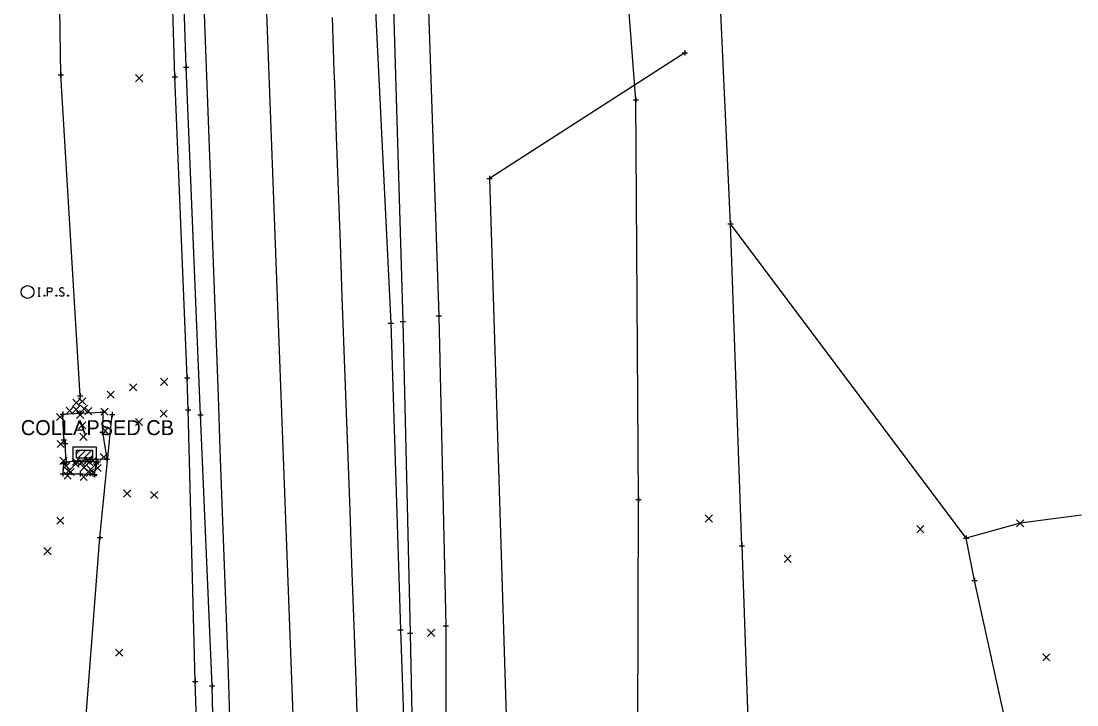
# Model space of a CAD drawing. Extents: x 146022 to 147632, y 437624 to 440659.
# Drawn here: x 146969.6 to 147167.5, y 438729.9 to 438858 of the extents above; entities that cross this region are included whole.
import ezdxf

# ---------------------------------------------------------------- set-up
doc = ezdxf.new("R2010")
doc.units = 0
for name, color, linetype in [('_CIVIL_CONSTRUCTION', 7, 'Continuous'), ('BR_P_Rail_Object', 7, 'Continuous'), ('DR_P_Ditch', 7, 'Continuous'), ('DR_P_Paved_Gutter', 7, 'Continuous'), ('DT_X_Triangles', 7, 'Continuous'), ('PF_X_Ground_Line', 7, 'Continuous'), ('PV_P_Curb', 7, 'Continuous'), ('PV_P_Saw_Cut_Line', 7, 'Continuous'), ('PV_P_Shoulder', 7, 'Continuous'), ('RD_P_Anchor_Assembly', 7, 'Continuous'), ('RD_P_Fence', 7, 'Continuous'), ('RD_P_GR_Lt_Replaced', 7, 'Continuous'), ('SC_Scratch3', 7, 'Continuous'), ('SV_X_Terrain_Boundary', 7, 'Continuous'), ('UT_X_Electric', 7, 'Continuous')]:
    doc.layers.add(name, color=color, linetype=linetype)

msp = doc.modelspace()

# ---------------------------------------------------------------- linework, layer by layer
at = {"layer": '_CIVIL_CONSTRUCTION'}
for p, q in [((146991.1, 438846.68), (146992.43, 438848.02)), ((146991.1, 438848.02), (146992.43, 438846.68)), ((146995.79, 438789.8), (146997.12, 438791.13)), ((146995.79, 438791.13), (146997.12, 438789.8)), ((146985.76, 438787.39), (146987.1, 438788.72)), ((146985.76, 438788.72), (146987.1, 438787.39)), ((146989.96, 438788.77), (146991.3, 438790.1)), ((146989.96, 438790.1), (146991.3, 438788.77)), ((146979.32, 438785.87), (146980.65, 438787.21)), ((146979.32, 438787.21), (146980.65, 438785.87)), ((146980.42, 438786.12), (146981.75, 438787.45)), ((146980.42, 438787.45), (146981.75, 438786.12)), ((146976.3, 438783.22), (146977.63, 438784.55)), ((146976.3, 438784.55), (146977.63, 438783.22)), ((146978.08, 438784.4), (146979.42, 438785.73)), ((146978.08, 438785.73), (146979.42, 438784.4)), ((146979.3, 438784.6), (146980.63, 438785.93)), ((146979.3, 438785.93), (146980.63, 438784.6)), ((146980.04, 438783.56), (146981.37, 438784.9)), ((146980.04, 438784.9), (146981.37, 438783.56)), ((146980.78, 438784.73), (146982.11, 438786.07)), ((146980.78, 438786.07), (146982.11, 438784.73)), ((146981.57, 438784.28), (146982.91, 438785.62)), ((146981.57, 438785.62), (146982.91, 438784.28)), ((146984.6, 438784.21), (146985.93, 438785.55)), ((146984.6, 438785.55), (146985.93, 438784.21)), ((146995.7, 438783.82), (146997.03, 438785.16)), ((146995.7, 438785.16), (146997.03, 438783.82)), ((146980.43, 438781.66), (146981.76, 438782.99)), ((146980.43, 438782.99), (146981.76, 438781.66)), ((146991.05, 438782.26), (146992.38, 438783.6)), ((146991.05, 438783.6), (146992.38, 438782.26)), ((146980.67, 438779.48), (146982, 438780.81)), ((146980.67, 438780.81), (146982, 438779.48)), ((146984.78, 438780.61), (146986.11, 438781.95)), ((146984.78, 438781.95), (146986.11, 438780.61)), ((146976.39, 438778.13), (146977.72, 438779.46)), ((146976.39, 438779.46), (146977.72, 438778.13)), ((146984.49, 438775.71), (146985.82, 438777.04)), ((146984.49, 438777.04), (146985.82, 438775.71)), ((146976.92, 438774.99), (146978.25, 438776.33)), ((146976.92, 438776.33), (146978.25, 438774.99)), ((146977.43, 438774.01), (146978.76, 438775.34)), ((146977.43, 438775.34), (146978.76, 438774.01)), ((146979.19, 438774.38), (146980.52, 438775.72)), ((146979.19, 438775.72), (146980.52, 438774.38)), ((146979.29, 438774.82), (146980.63, 438776.16)), ((146979.29, 438776.16), (146980.63, 438774.82)), ((146980.24, 438774.64), (146981.58, 438775.97)), ((146980.24, 438775.97), (146981.58, 438774.64)), ((146980.76, 438773.7), (146982.09, 438775.04)), ((146980.76, 438775.04), (146982.09, 438773.7)), ((146981.47, 438775.01), (146982.81, 438776.35)), ((146981.47, 438776.35), (146982.81, 438775.01)), ((146981.77, 438774.8), (146983.1, 438776.14)), ((146981.77, 438776.14), (146983.1, 438774.8)), ((146982, 438773.37), (146983.34, 438774.71)), ((146982, 438774.71), (146983.34, 438773.37)), ((146982.44, 438775.02), (146983.78, 438776.35)), ((146982.44, 438776.35), (146983.78, 438775.02)), ((146983.33, 438773.64), (146984.66, 438774.98)), ((146983.33, 438774.98), (146984.66, 438773.64)), ((146977.71, 438772.19), (146979.04, 438773.53)), ((146977.71, 438773.53), (146979.04, 438772.19)), ((146977.85, 438773.06), (146979.19, 438774.39)), ((146977.85, 438774.39), (146979.19, 438773.06)), ((146978.23, 438772.88), (146979.57, 438774.22)), ((146978.23, 438774.22), (146979.57, 438772.88)), ((146980.72, 438772), (146982.05, 438773.34)), ((146980.72, 438773.34), (146982.05, 438772)), ((146981.85, 438772.74), (146983.19, 438774.07)), ((146981.85, 438774.07), (146983.19, 438772.74)), ((146982.47, 438772.79), (146983.8, 438774.13)), ((146982.47, 438774.13), (146983.8, 438772.79)), ((146988.86, 438768.87), (146990.19, 438770.2)), ((146988.86, 438770.2), (146990.19, 438768.87)), ((146993.92, 438768.59), (146995.25, 438769.92)), ((146993.92, 438769.92), (146995.25, 438768.59)), ((146976.33, 438763.79), (146977.66, 438765.12)), ((146976.33, 438765.12), (146977.66, 438763.79)), ((147097.85, 438764.19), (147099.18, 438765.53)), ((147097.85, 438765.53), (147099.18, 438764.19)), ((147156.18, 438763.29), (147157.51, 438764.62)), ((147156.18, 438764.62), (147157.51, 438763.29)), ((147137.49, 438762.18), (147138.82, 438763.51)), ((147137.49, 438763.51), (147138.82, 438762.18)), ((146973.93, 438758.06), (146975.26, 438759.39)), ((146973.93, 438759.39), (146975.26, 438758.06)), ((147112.59, 438756.63), (147113.93, 438757.97)), ((147112.59, 438757.97), (147113.93, 438756.63)), ((147045.82, 438742.77), (147047.16, 438744.11)), ((147045.82, 438744.11), (147047.16, 438742.77)), ((146987.36, 438739.03), (146988.7, 438740.36)), ((146987.36, 438740.36), (146988.7, 438739.03)), ((147161.08, 438738.19), (147162.41, 438739.52)), ((147161.08, 438739.52), (147162.41, 438738.19))]:
    msp.add_line(p, q, dxfattribs=at)
at = {"layer": 'BR_P_Rail_Object'}
msp.add_line((147104.68, 438759.74), (147106.24, 438715.81), dxfattribs=at)
msp.add_lwpolyline([(147104.68, 438759.74), (147102.54, 438820.06), (147100.44, 438866.47)], dxfattribs=at)
at = {"layer": 'DR_P_Ditch'}
msp.add_lwpolyline([(146977.67, 438779.6), (146977.47, 438784.37), (146980.65, 438784.61), (146984.96, 438784.76), (146984.9, 438781.03), (146985.73, 438775.96), (146981.77, 438775.83), (146978.11, 438775.41), (146977.88, 438778.92)], close=True, dxfattribs=at)
at = {"layer": 'DR_P_Paved_Gutter'}
msp.add_lwpolyline([(146978.6, 438595.67), (146978.94, 438641.64), (146979.94, 438703.5), (146984.39, 438761.32), (146986.69, 438784.31)], dxfattribs=at)
at = {"layer": 'DT_X_Triangles'}
for p, q in [((146980.04, 438776.88), (146980.04, 438776.88)), ((146981.54, 438778.29), (146981.54, 438778.29)), ((146981.54, 438777.63), (146981.54, 438777.63)), ((146981.54, 438777.63), (146981.54, 438777.63)), ((146981.54, 438777.63), (146981.54, 438777.63)), ((146981.54, 438776.88), (146981.54, 438776.88)), ((146983.04, 438776.88), (146983.04, 438776.88)), ((146981.54, 438776.13), (146981.54, 438776.13)), ((146981.54, 438775.46), (146981.54, 438775.46))]:
    msp.add_line(p, q, dxfattribs=at)
at = {"layer": 'PF_X_Ground_Line'}
for points in [[(147083.77, 438607.47), (147085.36, 438645.7), (147085.38, 438653.03), (147087.42, 438661.11), (147093.01, 438666.12), (147091.72, 438683.75), (147085.16, 438703.04), (147085.35, 438768.44), (147084.84, 438843.3), (147077.73, 438936.13), (147068.93, 439004.24), (147064.53, 439058.96), (147057.49, 439104.29)], [(147000.94, 438785.22), (147000.76, 438791.19), (146998.48, 438847.62), (146996.47, 438915.01), (146994.92, 438975.08), (146992.24, 439037.6), (146990.54, 439100.99)], [(147031.27, 439100.49), (147033.12, 439049.69), (147035.54, 438989.57), (147036.95, 438926.08), (147039.28, 438864.72), (147041.14, 438801.73), (147042.54, 438743.36), (147043.21, 438709.89), (147047.27, 438680.18), (147046.71, 438662.18), (147051.05, 438666.42), (147056.82, 438665.98), (147058.21, 438672.79), (147056.9, 438679.13), (147056.31, 438685.27)], [(147004.32, 438675.01), (147002.25, 438734.29), (147000.94, 438785.22)], [(146977.61, 438775.16), (146977.47, 438773.23), (146980.69, 438773.25), (146983.38, 438773.1), (146983.73, 438775.07), (146984, 438775.44)]]:
    msp.add_lwpolyline(points, dxfattribs=at)
at = {"layer": 'PV_P_Curb'}
msp.add_lwpolyline([(147023.6, 438649.73), (147023.22, 438659.73), (147022.84, 438669.72), (147022.47, 438679.71), (147022.09, 438689.71), (147021.71, 438699.7), (147021.33, 438709.69), (147020.96, 438719.68), (147020.58, 438729.68), (147020.2, 438739.67), (147019.82, 438749.66), (147019.45, 438759.66), (147019.07, 438769.65), (147018.69, 438779.64), (147018.31, 438789.63), (147017.94, 438799.63), (147017.56, 438809.62), (147017.18, 438819.61), (147016.8, 438829.61), (147016.43, 438839.6), (147016.05, 438849.59), (147015.67, 438859.58)], dxfattribs=at)
at = {"layer": 'PV_P_Saw_Cut_Line'}
msp.add_lwpolyline([(147094.02, 438852.12), (147057.42, 438828.57), (147061.07, 438709.68), (147089.48, 438706.5), (147094.29, 438706.69)], dxfattribs=at)
at = {"layer": 'PV_P_Shoulder'}
for points in [[(146972.87, 438808.08), (146973.22, 438808.08)], [(146972.87, 438806.48), (146973.22, 438806.48)], [(146973.04, 438806.48), (146973.04, 438808.08)], [(146974, 438806.7), (146974.06, 438806.7), (146974.09, 438806.67), (146974.12, 438806.62), (146974.12, 438806.56), (146974.09, 438806.51), (146974.06, 438806.48), (146974, 438806.48), (146973.97, 438806.51), (146973.94, 438806.56), (146973.94, 438806.62), (146973.97, 438806.67), (146974, 438806.7)], [(146974.61, 438806.48), (146974.61, 438808.08), (146975.14, 438808.08), (146975.19, 438808.07), (146975.27, 438808.05), (146975.3, 438808.02), (146975.34, 438808), (146975.38, 438807.93), (146975.41, 438807.87), (146975.44, 438807.77), (146975.44, 438807.62), (146975.42, 438807.57), (146975.4, 438807.49), (146975.36, 438807.4), (146975.31, 438807.37), (146975.28, 438807.34), (146975.23, 438807.32), (146975.14, 438807.3), (146974.61, 438807.3)], [(146976.25, 438806.7), (146976.31, 438806.7), (146976.34, 438806.67), (146976.37, 438806.62), (146976.37, 438806.56), (146976.34, 438806.51), (146976.31, 438806.48), (146976.25, 438806.48), (146976.22, 438806.51), (146976.18, 438806.56), (146976.18, 438806.62), (146976.22, 438806.67), (146976.25, 438806.7)], [(146977.62, 438807.97), (146977.6, 438808), (146977.56, 438808.02), (146977.46, 438808.06), (146977.34, 438808.08), (146977.25, 438808.08), (146977.22, 438808.08), (146977.08, 438808.05), (146976.96, 438807.97), (146976.88, 438807.87), (146976.86, 438807.77), (146976.86, 438807.69), (146976.88, 438807.59), (146976.97, 438807.5), (146977.57, 438807.13), (146977.63, 438807.08), (146977.65, 438807.03), (146977.67, 438806.95), (146977.67, 438806.87), (146977.66, 438806.8), (146977.65, 438806.75), (146977.63, 438806.69), (146977.61, 438806.64), (146977.58, 438806.6), (146977.55, 438806.56), (146977.52, 438806.53), (146977.47, 438806.51), (146977.44, 438806.5), (146977.34, 438806.48), (146977.19, 438806.48), (146977.09, 438806.51), (146976.95, 438806.6), (146976.86, 438806.67)], [(146978.43, 438806.7), (146978.49, 438806.7), (146978.52, 438806.67), (146978.55, 438806.62), (146978.55, 438806.56), (146978.52, 438806.51), (146978.49, 438806.48), (146978.43, 438806.48), (146978.4, 438806.51), (146978.37, 438806.56), (146978.37, 438806.62), (146978.4, 438806.67), (146978.43, 438806.7)]]:
    msp.add_lwpolyline(points, dxfattribs=at)
msp.add_circle((146970.85, 438807.28), 1.2, dxfattribs=at)
at = {"layer": 'RD_P_Anchor_Assembly'}
for p, q in [((147093.52, 438852.12), (147094.52, 438852.12)), ((147094.02, 438852.62), (147094.02, 438851.62)), ((147094.02, 438852.12), (147094.02, 438852.12)), ((147000.58, 438849.92), (147000.58, 438848.92)), ((146976.61, 438847.98), (146977.61, 438847.98)), ((146977.11, 438848.48), (146977.11, 438847.48)), ((146977.11, 438847.98), (146977.11, 438847.98)), ((146998.48, 438848.12), (146998.48, 438847.12)), ((147000.08, 438849.42), (147001.08, 438849.42)), ((147000.58, 438849.42), (147000.58, 438849.42)), ((146997.98, 438847.62), (146998.98, 438847.62)), ((146998.48, 438847.62), (146998.48, 438847.62)), ((147084.84, 438843.8), (147084.84, 438842.8)), ((147084.34, 438843.3), (147085.34, 438843.3)), ((147084.84, 438843.3), (147084.84, 438843.3)), ((147056.92, 438828.57), (147057.92, 438828.57)), ((147057.42, 438829.07), (147057.42, 438828.07)), ((147057.42, 438828.57), (147057.42, 438828.57)), ((147102.04, 438820.06), (147103.04, 438820.06)), ((147102.54, 438820.56), (147102.54, 438819.56)), ((147102.54, 438820.06), (147102.54, 438820.06)), ((147041.14, 438802.23), (147041.14, 438801.23)), ((147047.43, 438802.84), (147048.43, 438802.84)), ((147047.93, 438803.34), (147047.93, 438802.34)), ((147047.93, 438802.84), (147047.93, 438802.84)), ((147038.44, 438801.43), (147039.44, 438801.43)), ((147038.94, 438801.93), (147038.94, 438800.93)), ((147038.94, 438801.43), (147038.94, 438801.43)), ((147040.64, 438801.73), (147041.64, 438801.73)), ((147041.14, 438801.73), (147041.14, 438801.73)), ((147000.26, 438791.19), (147001.26, 438791.19)), ((147000.76, 438791.69), (147000.76, 438790.69)), ((147000.76, 438791.19), (147000.76, 438791.19)), ((146980.23, 438787.82), (146981.23, 438787.82)), ((146980.73, 438788.32), (146980.73, 438787.32)), ((146980.73, 438787.82), (146980.73, 438787.82)), ((146977.47, 438784.87), (146977.47, 438783.87)), ((146980.15, 438784.61), (146981.15, 438784.61)), ((146980.65, 438785.11), (146980.65, 438784.11)), ((146980.65, 438784.61), (146980.65, 438784.61)), ((146984.46, 438784.76), (146985.46, 438784.76)), ((146984.96, 438785.26), (146984.96, 438784.26)), ((146984.96, 438784.76), (146984.96, 438784.76)), ((146986.69, 438784.81), (146986.69, 438783.81)), ((147000.44, 438785.22), (147001.44, 438785.22)), ((147000.94, 438785.72), (147000.94, 438784.72)), ((147000.94, 438785.22), (147000.94, 438785.22)), ((147003.27, 438784.8), (147003.27, 438783.8)), ((146976.97, 438784.37), (146977.97, 438784.37)), ((146977.47, 438784.37), (146977.47, 438784.37)), ((146986.19, 438784.31), (146987.19, 438784.31)), ((146986.69, 438784.31), (146986.69, 438784.31)), ((147002.77, 438784.3), (147003.77, 438784.3)), ((147003.27, 438784.3), (147003.27, 438784.3)), ((146984.4, 438781.03), (146985.4, 438781.03)), ((146984.9, 438781.53), (146984.9, 438780.53)), ((146984.9, 438781.03), (146984.9, 438781.03)), ((146977.17, 438779.6), (146978.17, 438779.6)), ((146977.38, 438778.92), (146978.38, 438778.92)), ((146977.67, 438780.1), (146977.67, 438779.1)), ((146977.67, 438779.6), (146977.67, 438779.6)), ((146977.88, 438779.42), (146977.88, 438778.42)), ((146977.88, 438778.92), (146977.88, 438778.92)), ((146977.11, 438775.16), (146978.11, 438775.16)), ((146977.61, 438775.66), (146977.61, 438774.66)), ((146977.61, 438775.41), (146978.61, 438775.41)), ((146977.61, 438775.16), (146977.61, 438775.16)), ((146978.11, 438775.91), (146978.11, 438774.91)), ((146978.11, 438775.41), (146978.11, 438775.41)), ((146981.27, 438775.83), (146982.27, 438775.83)), ((146981.77, 438776.33), (146981.77, 438775.33)), ((146981.77, 438775.83), (146981.77, 438775.83)), ((146983.23, 438775.07), (146984.23, 438775.07)), ((146983.5, 438775.44), (146984.5, 438775.44)), ((146983.73, 438775.57), (146983.73, 438774.57)), ((146983.73, 438775.07), (146983.73, 438775.07)), ((146984, 438775.94), (146984, 438774.94)), ((146984, 438775.44), (146984, 438775.44)), ((146985.23, 438775.96), (146986.23, 438775.96)), ((146985.73, 438776.46), (146985.73, 438775.46)), ((146985.73, 438775.96), (146985.73, 438775.96)), ((146976.97, 438773.23), (146977.97, 438773.23)), ((146977.47, 438773.73), (146977.47, 438772.73)), ((146977.47, 438773.23), (146977.47, 438773.23)), ((146980.19, 438773.25), (146981.19, 438773.25)), ((146980.69, 438773.75), (146980.69, 438772.75)), ((146980.69, 438773.25), (146980.69, 438773.25)), ((146982.88, 438773.1), (146983.88, 438773.1)), ((146983.38, 438773.6), (146983.38, 438772.6)), ((146983.38, 438773.1), (146983.38, 438773.1)), ((147085.35, 438768.94), (147085.35, 438767.94)), ((147084.85, 438768.44), (147085.85, 438768.44)), ((147085.35, 438768.44), (147085.35, 438768.44)), ((146983.89, 438761.32), (146984.89, 438761.32)), ((146984.39, 438761.82), (146984.39, 438760.82)), ((146984.39, 438761.32), (146984.39, 438761.32)), ((147146.21, 438761.18), (147147.21, 438761.18)), ((147146.71, 438761.68), (147146.71, 438760.68)), ((147146.71, 438761.18), (147146.71, 438761.18)), ((147104.18, 438759.74), (147105.18, 438759.74)), ((147104.68, 438760.24), (147104.68, 438759.24)), ((147104.68, 438759.74), (147104.68, 438759.74)), ((147147.77, 438753.21), (147148.77, 438753.21)), ((147148.27, 438753.71), (147148.27, 438752.71)), ((147148.27, 438753.21), (147148.27, 438753.21)), ((147049.2, 438745.24), (147049.2, 438744.24)), ((147040.23, 438744.01), (147041.23, 438744.01)), ((147040.73, 438744.51), (147040.73, 438743.51)), ((147040.73, 438744.01), (147040.73, 438744.01)), ((147042.04, 438743.36), (147043.04, 438743.36)), ((147042.54, 438743.86), (147042.54, 438742.86)), ((147042.54, 438743.36), (147042.54, 438743.36)), ((147048.7, 438744.74), (147049.7, 438744.74)), ((147049.2, 438744.74), (147049.2, 438744.74)), ((147001.75, 438734.29), (147002.75, 438734.29)), ((147002.25, 438734.79), (147002.25, 438733.79)), ((147002.25, 438734.29), (147002.25, 438734.29)), ((147004.94, 438733.48), (147005.94, 438733.48)), ((147005.44, 438733.98), (147005.44, 438732.98)), ((147005.44, 438733.48), (147005.44, 438733.48))]:
    msp.add_line(p, q, dxfattribs=at)
at = {"layer": 'RD_P_Fence'}
for points in [[(147038.4, 439102.6), (147039.77, 439045.27), (147042.11, 438990.25), (147044.49, 438926.83), (147045.82, 438865.74), (147047.93, 438802.84), (147049.2, 438744.74), (147049.15, 438710.72), (147051.96, 438684.33), (147053.35, 438672.49)], [(146980.73, 438787.82), (146977.11, 438847.98), (146976.07, 438914.02), (146974.05, 438975.88), (146972.15, 439037.23), (146971.5, 439100.04)]]:
    msp.add_lwpolyline(points, dxfattribs=at)
at = {"layer": 'RD_P_GR_Lt_Replaced'}
for points in [[(147007.62, 438631.92), (147006.83, 438674.73), (147005.44, 438733.48), (147003.27, 438784.3), (147000.58, 438849.42), (146998.52, 438912.12), (146996.34, 438976.53), (146994.65, 439039.1), (146992.53, 439098.48), (146992.61, 439099.81)], [(147028.78, 439100.29), (147030.7, 439050.1), (147032.83, 438989.57), (147034.21, 438926.71), (147035.77, 438865.15), (147038.94, 438801.43), (147040.73, 438744.01), (147041.91, 438709.75), (147043.37, 438678.61), (147045.13, 438660.08), (147045.68, 438643.98), (147046.17, 438628.21), (147046.87, 438610.99), (147047.32, 438600.78)], [(147092.64, 438642.79), (147097.75, 438641.08), (147115.71, 438640.44), (147138.8, 438641.73), (147148.43, 438645.08), (147158.29, 438653.26), (147161.17, 438662.69), (147161.89, 438681.2), (147158.79, 438705.43), (147148.27, 438753.21), (147146.71, 438761.18)]]:
    msp.add_lwpolyline(points, dxfattribs=at)
at = {"layer": 'SC_Scratch3'}
for points in [[(147011.66, 438647.83), (147011.3, 438657.83), (147010.94, 438667.82), (147010.58, 438677.81), (147010.22, 438687.81), (147009.86, 438697.8), (147009.5, 438707.79), (147009.14, 438717.79), (147008.78, 438727.78), (147008.42, 438737.77), (147008.06, 438747.77), (147007.69, 438757.76), (147007.33, 438767.75), (147006.97, 438777.75), (147006.61, 438787.74), (147006.25, 438797.73), (147005.89, 438807.73), (147005.53, 438817.72), (147005.17, 438827.71), (147004.81, 438837.71), (147004.45, 438847.7), (147004.09, 438857.7), (147003.72, 438867.69)], [(147027.9, 438858.71), (147028.25, 438848.72), (147028.34, 438846.33), (147028.7, 438836.33), (147029.05, 438826.34), (147029.41, 438816.35), (147029.77, 438806.35), (147030.13, 438796.36), (147030.49, 438786.36), (147030.85, 438776.37), (147031.21, 438766.38), (147031.57, 438756.38), (147031.93, 438746.39), (147032.29, 438736.4), (147032.64, 438726.4), (147033, 438716.41), (147033.36, 438706.42), (147033.72, 438696.42), (147034.08, 438686.43), (147034.44, 438676.44), (147034.77, 438667.24), (147035.15, 438657.25), (147035.5, 438648.06)]]:
    msp.add_lwpolyline(points, dxfattribs=at)
at = {"layer": 'SV_X_Terrain_Boundary'}
msp.add_lwpolyline([(147168.32, 438765.47), (147156.85, 438763.96), (147146.71, 438761.18), (147102.54, 438820.06), (147100.44, 438866.47)], dxfattribs=at)
at = {"layer": 'UT_X_Electric'}
for p, q in [((146980.04, 438777.63), (146980.55, 438777.63)), ((146980.04, 438777.06), (146980.04, 438777.63)), ((146980.04, 438777.04), (146980.63, 438777.63)), ((146980.04, 438776.13), (146980.04, 438776.69)), ((146980.26, 438776.13), (146981.76, 438777.63)), ((146980.93, 438777.63), (146981.35, 438777.63)), ((146981.39, 438776.13), (146982.89, 438777.63)), ((146981.76, 438777.63), (146982.15, 438777.63)), ((146982.52, 438776.13), (146983.04, 438776.65)), ((146982.53, 438777.63), (146983.04, 438777.63)), ((146983.04, 438777.63), (146983.04, 438777.06)), ((146983.04, 438776.69), (146983.04, 438776.13)), ((146980.55, 438776.13), (146980.04, 438776.13)), ((146981.35, 438776.13), (146980.93, 438776.13)), ((146982.15, 438776.13), (146981.73, 438776.13)), ((146983.04, 438776.13), (146982.53, 438776.13))]:
    msp.add_line(p, q, dxfattribs=at)
for points in [[(146979.37, 438778.29), (146983.71, 438778.29), (146983.71, 438775.46), (146979.37, 438775.46)], [(146980.04, 438777.63), (146983.04, 438777.63), (146983.04, 438776.13), (146980.04, 438776.13)], [(146980.04, 438777.63), (146983.04, 438777.63), (146983.04, 438776.13), (146980.04, 438776.13)]]:
    msp.add_lwpolyline(points, close=True, dxfattribs=at)

# ---------------------------------------------------------------- texts
at = {"layer": 'DR_P_Ditch'}
msp.add_text('COLLAPSED CB', height=2.8, dxfattribs=at).set_placement((146969.59, 438780.47))

doc.saveas('drawing.dxf')
